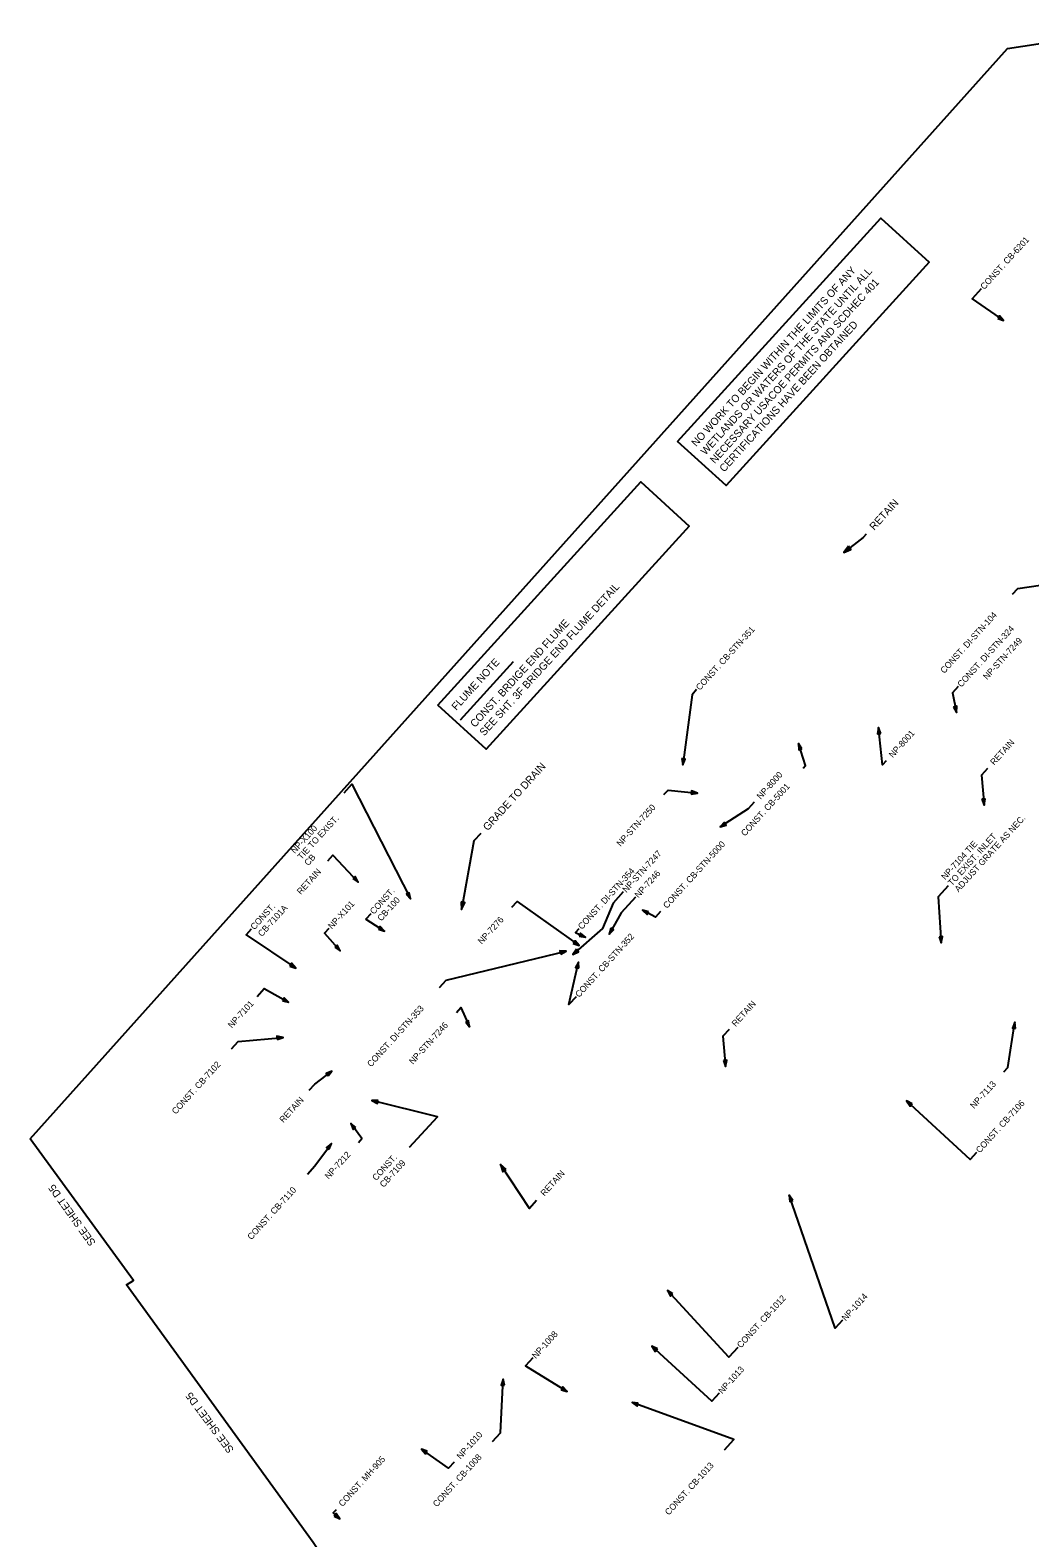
# Model space of a CAD drawing. Extents: x 1608866 to 1610566, y 1091738 to 1093850.
# Drawn here: x 1608866 to 1609658, y 1092457 to 1093652 of the extents above; entities that cross this region are included whole.
import ezdxf

# ---------------------------------------------------------------- set-up
doc = ezdxf.new("R2010")
doc.units = 0
for name, color, linetype in [('NOI', 7, 'Continuous'), ('Plan_Clip', 7, 'Continuous'), ('RD_SHT_MatchLine', 7, 'Continuous'), ('RD_TX_Drainage', 7, 'Continuous')]:
    doc.layers.add(name, color=color, linetype=linetype)

msp = doc.modelspace()

# ---------------------------------------------------------------- linework, layer by layer
at = {"layer": 'NOI'}
for points in [[(1609379, 1093326.2), (1609540, 1093503.2), (1609578.4, 1093468.3), (1609417.4, 1093291.3)], [(1609188.8, 1093117.1), (1609349.8, 1093294.1), (1609388.2, 1093259.2), (1609227.2, 1093082.2)]]:
    msp.add_lwpolyline(points, close=True, dxfattribs=at)
at = {"layer": 'Plan_Clip'}
msp.add_lwpolyline([(1608865.5, 1092773.4), (1609640.6, 1093637.6), (1609736, 1093652.2), (1609859.4, 1093621.4), (1610115.1, 1093602.3), (1610196.6, 1093489.1), (1610193.3, 1093486.6), (1610273.8, 1093378.2), (1610243.5, 1093357.4), (1610329.6, 1093201), (1610402.7, 1093068.4), (1609510.9, 1092089.3), (1609496.9, 1092101.7), (1609489.5, 1092107.9), (1609480.6, 1092093.3), (1609450.3, 1092116), (1609446.7, 1092111), (1609379.8, 1092159.3), (1609135.6, 1092347), (1609149.6, 1092364.4), (1609090, 1092453.4), (1608942, 1092657.6), (1608947.4, 1092661.1)], close=True, dxfattribs=at)
msp.add_lwpolyline([(1608865.5, 1092773.4), (1609640.6, 1093637.6), (1609736, 1093652.2), (1609859.4, 1093621.4), (1610115.1, 1093602.3), (1610196.6, 1093489.1), (1610193.3, 1093486.6), (1610273.8, 1093378.2), (1610243.5, 1093357.4), (1610329.6, 1093201), (1610402.7, 1093068.4), (1609510.9, 1092089.3), (1609496.9, 1092101.7), (1609489.5, 1092107.9), (1609480.6, 1092093.3), (1609450.3, 1092116), (1609446.7, 1092111), (1609379.8, 1092159.3), (1609135.6, 1092347), (1609149.6, 1092364.4), (1609090, 1092453.4), (1608942, 1092657.6), (1608947.4, 1092661.1)], close=True, dxfattribs=at)
msp.add_lwpolyline([(1608865.5, 1092773.4), (1609640.6, 1093637.6), (1609736, 1093652.2), (1609859.4, 1093621.4), (1610115.1, 1093602.3), (1610196.6, 1093489.1), (1610193.3, 1093486.6), (1610273.8, 1093378.2), (1610243.5, 1093357.4), (1610329.6, 1093201), (1610402.7, 1093068.4), (1609510.9, 1092089.3), (1609496.9, 1092101.7), (1609489.5, 1092107.9), (1609480.6, 1092093.3), (1609450.3, 1092116), (1609446.7, 1092111), (1609379.8, 1092159.3), (1609135.6, 1092347), (1609149.6, 1092364.4), (1609090, 1092453.4), (1608942, 1092657.6), (1608947.4, 1092661.1)], close=True, dxfattribs=at)
msp.add_lwpolyline([(1608865.5, 1092773.4), (1609640.6, 1093637.6), (1609736, 1093652.2), (1609859.4, 1093621.4), (1610115.1, 1093602.3), (1610196.6, 1093489.1), (1610193.3, 1093486.6), (1610273.8, 1093378.2), (1610243.5, 1093357.4), (1610329.6, 1093201), (1610402.7, 1093068.4), (1609510.9, 1092089.3), (1609496.9, 1092101.7), (1609489.5, 1092107.9), (1609480.6, 1092093.3), (1609450.3, 1092116), (1609446.7, 1092111), (1609379.8, 1092159.3), (1609135.6, 1092347), (1609149.6, 1092364.4), (1609090, 1092453.4), (1608942, 1092657.6), (1608947.4, 1092661.1)], close=True, dxfattribs=at)
msp.add_lwpolyline([(1608865.5, 1092773.4), (1609640.6, 1093637.6), (1609736, 1093652.2), (1609859.4, 1093621.4), (1610115.1, 1093602.3), (1610196.6, 1093489.1), (1610193.3, 1093486.6), (1610273.8, 1093378.2), (1610243.5, 1093357.4), (1610329.6, 1093201), (1610402.7, 1093068.4), (1609510.9, 1092089.3), (1609496.9, 1092101.7), (1609489.5, 1092107.9), (1609480.6, 1092093.3), (1609450.3, 1092116), (1609446.7, 1092111), (1609379.8, 1092159.3), (1609135.6, 1092347), (1609149.6, 1092364.4), (1609090, 1092453.4), (1608942, 1092657.6), (1608947.4, 1092661.1)], close=True, dxfattribs=at)
msp.add_lwpolyline([(1608865.5, 1092773.4), (1609640.6, 1093637.6), (1609736, 1093652.2), (1609859.4, 1093621.4), (1610115.1, 1093602.3), (1610196.6, 1093489.1), (1610193.3, 1093486.6), (1610273.8, 1093378.2), (1610243.5, 1093357.4), (1610329.6, 1093201), (1610402.7, 1093068.4), (1609510.9, 1092089.3), (1609496.9, 1092101.7), (1609489.5, 1092107.9), (1609480.6, 1092093.3), (1609450.3, 1092116), (1609446.7, 1092111), (1609379.8, 1092159.3), (1609135.6, 1092347), (1609149.6, 1092364.4), (1609090, 1092453.4), (1608942, 1092657.6), (1608947.4, 1092661.1)], close=True, dxfattribs=at)
msp.add_lwpolyline([(1608865.5, 1092773.4), (1609640.6, 1093637.6), (1609736, 1093652.2), (1609859.4, 1093621.4), (1610115.1, 1093602.3), (1610196.6, 1093489.1), (1610193.3, 1093486.6), (1610273.8, 1093378.2), (1610243.5, 1093357.4), (1610329.6, 1093201), (1610402.7, 1093068.4), (1609510.9, 1092089.3), (1609496.9, 1092101.7), (1609489.5, 1092107.9), (1609480.6, 1092093.3), (1609450.3, 1092116), (1609446.7, 1092111), (1609379.8, 1092159.3), (1609135.6, 1092347), (1609149.6, 1092364.4), (1609090, 1092453.4), (1608942, 1092657.6), (1608947.4, 1092661.1)], close=True, dxfattribs=at)
msp.add_lwpolyline([(1608865.5, 1092773.4), (1609640.6, 1093637.6), (1609736, 1093652.2), (1609859.4, 1093621.4), (1610115.1, 1093602.3), (1610196.6, 1093489.1), (1610193.3, 1093486.6), (1610273.8, 1093378.2), (1610243.5, 1093357.4), (1610329.6, 1093201), (1610402.7, 1093068.4), (1609510.9, 1092089.3), (1609496.9, 1092101.7), (1609489.5, 1092107.9), (1609480.6, 1092093.3), (1609450.3, 1092116), (1609446.7, 1092111), (1609379.8, 1092159.3), (1609135.6, 1092347), (1609149.6, 1092364.4), (1609090, 1092453.4), (1608942, 1092657.6), (1608947.4, 1092661.1)], close=True, dxfattribs=at)
at = {"layer": 'RD_TX_Drainage'}
msp.add_line((1609206.9, 1093105.6), (1609248.9, 1093151.7), dxfattribs=at)
for points in [[(1609619.7, 1093447.1), (1609612.5, 1093439.2), (1609637.5, 1093422)], [(1609528.4, 1093252.7), (1609526, 1093250.1), (1609510.8, 1093238.3)], [(1609644.6, 1093205.2), (1609648.8, 1093209.8), (1609742.1, 1093223.5)], [(1609601.5, 1093131.9), (1609596.9, 1093126.9), (1609600.1, 1093111.3)], [(1609394, 1093129.5), (1609390.4, 1093125.5), (1609383, 1093069.9)], [(1609544.4, 1093073.1), (1609541.4, 1093069.8), (1609538.3, 1093099.4)], [(1609478.4, 1093067.2), (1609480.5, 1093069.5), (1609474.7, 1093086.8)], [(1609624.8, 1093067.1), (1609620, 1093061.8), (1609622.1, 1093037.9)], [(1609114.5, 1093047.7), (1609120.6, 1093054.5), (1609167.1, 1092963.6)], [(1609368.1, 1093046.3), (1609371.4, 1093049.9), (1609394.8, 1093047.5)], [(1609439.7, 1093040.2), (1609434.9, 1093034.9), (1609412.8, 1093020.7)], [(1609222.8, 1093015.5), (1609217.5, 1093009.6), (1609207.7, 1092955.2)], [(1609101.5, 1092993.8), (1609105.6, 1092998.3), (1609125.6, 1092977)], [(1609335.9, 1092969.2), (1609327.8, 1092960.2), (1609319.4, 1092940.1), (1609296, 1092919.6)], [(1609345.5, 1092965), (1609334.1, 1092952.5), (1609331.6, 1092947.8), (1609324.6, 1092935.6)], [(1609593.4, 1092973.9), (1609585.5, 1092965.3), (1609587.9, 1092928.8)], [(1609135.6, 1092951.9), (1609131.8, 1092947.7), (1609146.5, 1092938)], [(1609247.4, 1092957), (1609251.7, 1092961.7), (1609300.8, 1092926.6)], [(1609365.4, 1092953.6), (1609361.4, 1092949.2), (1609351, 1092954.6)], [(1609102.3, 1092940.3), (1609099, 1092936.6), (1609111.3, 1092922.5)], [(1609300.6, 1092940), (1609297.9, 1092937), (1609305.8, 1092933.3)], [(1609040.9, 1092939.6), (1609036.8, 1092935.1), (1609076.2, 1092908.8)], [(1609190.1, 1092893.3), (1609195.5, 1092899.2), (1609290.7, 1092922.3)], [(1609298.4, 1092886.1), (1609292.8, 1092879.9), (1609300.4, 1092913.6)], [(1609045.5, 1092886.4), (1609051.1, 1092892.6), (1609070.5, 1092881.7)], [(1609203.5, 1092873.5), (1609207.1, 1092877.5), (1609214, 1092862.1)], [(1609419.8, 1092860), (1609414.9, 1092854.7), (1609417, 1092830.8)], [(1609637.6, 1092826.6), (1609640.7, 1092829.9), (1609646.4, 1092865.8)], [(1609025.2, 1092844.8), (1609030.4, 1092850.5), (1609066.2, 1092853.9)], [(1609086.7, 1092811.9), (1609091.2, 1092816.8), (1609104.9, 1092827.2)], [(1609166.4, 1092766.8), (1609188.5, 1092791), (1609136.5, 1092803.8)], [(1609616.1, 1092762.7), (1609611, 1092757.2), (1609560.6, 1092803.5)], [(1609125.8, 1092770.6), (1609128.5, 1092773.6), (1609119.9, 1092785.5)], [(1609085.4, 1092745.5), (1609091.3, 1092752), (1609104.5, 1092769.8)], [(1609267.2, 1092724.5), (1609261.5, 1092718.3), (1609238.4, 1092753.1)], [(1609509.8, 1092629.6), (1609504, 1092623.3), (1609467.5, 1092728.9)], [(1609426.7, 1092608.1), (1609419.7, 1092600.4), (1609370.9, 1092653.3)], [(1609411.9, 1092571.9), (1609406.2, 1092565.6), (1609358.6, 1092609.2)], [(1609264.1, 1092599.8), (1609258.3, 1092593.4), (1609291.4, 1092573.2)], [(1609232.2, 1092533.5), (1609238.5, 1092540.4), (1609240.7, 1092583)], [(1609416.2, 1092527), (1609423.6, 1092535.1), (1609342.8, 1092564.5)], [(1609201.7, 1092517.1), (1609197.4, 1092512.3), (1609175.8, 1092527.5)], [(1609108.1, 1092479.5), (1609105.7, 1092476.9), (1609111, 1092472.2)]]:
    msp.add_lwpolyline(points, dxfattribs=at)
for points in [[(1609632.8, 1093423.7), (1609637.5, 1093422), (1609634.3, 1093425.8)], [(1609514.4, 1093243.1), (1609510.8, 1093238.3), (1609516.3, 1093240.6)], [(1609597.8, 1093115.7), (1609600.1, 1093111.3), (1609600.4, 1093116.3)], [(1609540.1, 1093094.7), (1609538.3, 1093099.4), (1609537.5, 1093094.5)], [(1609477.4, 1093082.6), (1609474.7, 1093086.8), (1609475, 1093081.8)], [(1609382.4, 1093074.9), (1609383, 1093069.9), (1609384.9, 1093074.5)], [(1609389.8, 1093046.7), (1609394.8, 1093047.5), (1609390.1, 1093049.2)], [(1609620.3, 1093042.6), (1609622.1, 1093037.9), (1609622.9, 1093042.8)], [(1609416.2, 1093024.4), (1609412.8, 1093020.7), (1609417.6, 1093022.2)], [(1609121.3, 1092979.7), (1609125.6, 1092977), (1609123.2, 1092981.4)], [(1609163.8, 1092967.3), (1609167.1, 1092963.6), (1609166.1, 1092968.5)], [(1609207.2, 1092961.2), (1609207.7, 1092955.2), (1609210.2, 1092960.7)], [(1609355.9, 1092953.5), (1609351, 1092954.6), (1609354.7, 1092951.2)], [(1609141.7, 1092939.6), (1609146.5, 1092938), (1609143.2, 1092941.8)], [(1609325.9, 1092940.4), (1609324.6, 1092935.6), (1609328.1, 1092939.1)], [(1609296.2, 1092928.3), (1609300.8, 1092926.6), (1609297.7, 1092930.4)], [(1609300.9, 1092934.2), (1609305.8, 1092933.3), (1609302, 1092936.5)], [(1609586.3, 1092933.6), (1609587.9, 1092928.8), (1609588.9, 1092933.7)], [(1609107.1, 1092925.3), (1609111.3, 1092922.5), (1609109.1, 1092927)], [(1609286.3, 1092919.9), (1609290.7, 1092922.3), (1609285.7, 1092922.4)], [(1609298.8, 1092923.7), (1609296, 1092919.6), (1609300.5, 1092921.8)], [(1609071.4, 1092910.4), (1609076.2, 1092908.8), (1609072.9, 1092912.6)], [(1609300.6, 1092908.6), (1609300.4, 1092913.6), (1609298.1, 1092909.2)], [(1609065.6, 1092882.9), (1609070.5, 1092881.7), (1609066.9, 1092885.2)], [(1609210.9, 1092866), (1609214, 1092862.1), (1609213.2, 1092867.1)], [(1609646.9, 1092860.9), (1609646.4, 1092865.8), (1609644.4, 1092861.3)], [(1609061.5, 1092852.2), (1609066.2, 1092853.9), (1609061.2, 1092854.7)], [(1609415.3, 1092835.5), (1609417, 1092830.8), (1609417.9, 1092835.7)], [(1609101.8, 1092823.3), (1609104.9, 1092827.2), (1609100.2, 1092825.3)], [(1609141.5, 1092803.9), (1609136.5, 1092803.8), (1609140.9, 1092801.4)], [(1609565, 1092801.2), (1609560.6, 1092803.5), (1609563.3, 1092799.3)], [(1609123.8, 1092782.4), (1609119.9, 1092785.5), (1609121.7, 1092780.8)], [(1609102.7, 1092765.2), (1609104.5, 1092769.8), (1609100.6, 1092766.7)], [(1609242.9, 1092749.1), (1609238.4, 1092753.1), (1609240.3, 1092747.4)], [(1609470.3, 1092724.7), (1609467.5, 1092728.9), (1609467.9, 1092723.9)], [(1609375.2, 1092650.6), (1609370.9, 1092653.3), (1609373.3, 1092648.8)], [(1609363.1, 1092606.9), (1609358.6, 1092609.2), (1609361.3, 1092605)], [(1609241.7, 1092578.1), (1609240.7, 1092583), (1609239.1, 1092578.2)], [(1609286.6, 1092574.6), (1609291.4, 1092573.2), (1609287.9, 1092576.9)], [(1609347.8, 1092564), (1609342.8, 1092564.5), (1609346.9, 1092561.6)], [(1609180.5, 1092525.8), (1609175.8, 1092527.5), (1609179, 1092523.7)], [(1609106.5, 1092474.4), (1609111, 1092472.2), (1609108.2, 1092476.4)]]:
    msp.add_lwpolyline(points, close=True, dxfattribs=at)

# ---------------------------------------------------------------- texts
at = {"layer": 'NOI'}
for s, p in [('NO WORK TO BEGIN WITHIN THE LIMITS OF ANY', (1609393.7, 1093321.7)), ('WETLANDS OR WATERS OF THE STATE UNTIL ALL', (1609401.1, 1093315)), ('NECESSARY USACOE PERMITS AND SCDHEC 401', (1609408.5, 1093308.2)), ('CERTIFICATIONS HAVE BEEN OBTAINED', (1609415.9, 1093301.5)), ('SEE SHT. 3F BRIDGE END FLUME DETAIL', (1609225.7, 1093092.4)), ('CONST. BRDIGE END FLUME', (1609218.3, 1093099.1)), ('FLUME NOTE', (1609203.5, 1093112.6))]:
    msp.add_text(s, height=6, rotation=47.7153, dxfattribs=at).set_placement(p)
at = {"layer": 'RD_SHT_MatchLine'}
for rotation, p in [(125.5072, (1608917.8, 1092691.2)), (126.6022, (1609027.4, 1092527.1))]:
    msp.add_text('SEE SHEET D5', height=6, rotation=rotation, dxfattribs=at).set_placement(p)
at = {"layer": 'RD_TX_Drainage'}
for s, height, p in [('CONST. CB-6201', 5, (1609622.2, 1093446.2)), ('RETAIN', 6, (1609534.9, 1093255.4)), ('CONST. DI-STN-104', 5, (1609590.4, 1093141.9)), ('CONST. CB-STN-351', 5, (1609396.6, 1093128.5)), ('CONST. DI-STN-324', 5, (1609604, 1093131)), ('NP-STN-7249', 5, (1609624.4, 1093137)), ('NP-8001', 5, (1609549.6, 1093075.1)), ('RETAIN', 5, (1609630, 1093069.2)), ('GRADE TO DRAIN', 6, (1609228.4, 1093017.2)), ('NP-8000', 5, (1609444.9, 1093042.2)), ('CONST. CB-5001', 5, (1609432.4, 1093012.9)), ('NP-STN-7250', 5, (1609333.7, 1093004.8)), ('TIE TO EXIST.', 5, (1609080.8, 1092994.3)), (' ADJUST GRATE AS NEC.', 5, (1609600.5, 1092967.3)), ('NP-X100', 5, (1609075.4, 1092999.2)), (' TO EXIST. INLET', 5, (1609595.2, 1092972.2)), ('NP-STN-7247', 5, (1609338.4, 1092968.2)), ('CONST. CB-STN-5000', 5, (1609370.6, 1092955.6)), (' NP-7104 TIE', 5, (1609589.9, 1092977)), ('RETAIN', 5, (1609080.2, 1092966.7)), ('CB', 5, (1609086.1, 1092989.5)), ('CONST. DI-STN-354', 5, (1609303.1, 1092939)), ('NP-7246', 5, (1609348, 1092964)), ('CONST.', 5, (1609138.1, 1092951)), ('CB-100', 5, (1609144, 1092945.6)), ('CONST.', 5, (1609043.4, 1092938.7)), ('CB-7101A', 5, (1609049.3, 1092933.3)), ('NP-X101', 5, (1609104.9, 1092939.3)), ('NP-7276', 5, (1609223.7, 1092927.3)), ('CONST. CB-STN-352', 5, (1609300.9, 1092885.1)), ('NP-7101', 5, (1609025.5, 1092860.8)), ('RETAIN', 5, (1609425, 1092862)), ('CONST. DI-STN-353', 5, (1609135.9, 1092830)), ('NP-STN-7246', 5, (1609169.1, 1092832.1)), ('CONST. CB-7102', 5, (1608981, 1092792.5)), ('NP-7113', 5, (1609614.1, 1092797)), ('RETAIN', 5, (1609066.4, 1092785.8)), ('CONST. CB-7106', 5, (1609618.6, 1092761.8)), ('NP-7212', 5, (1609102.3, 1092741.1)), ('CONST.', 5, (1609140, 1092739.9)), ('CB-7109', 5, (1609145.9, 1092734.5)), ('RETAIN', 5, (1609273.4, 1092727.6)), ('CONST. CB-7110', 5, (1609041, 1092693)), ('CONST. CB-1012', 5, (1609429.2, 1092607.2)), ('NP-1014', 5, (1609512.3, 1092628.7)), ('NP-1008', 5, (1609266.6, 1092598.8)), ('NP-1013', 5, (1609414.4, 1092570.9)), ('NP-1010', 5, (1609206.9, 1092519.1)), ('CONST. MH-905', 5, (1609113.3, 1092481.5)), ('CONST. CB-1008', 5, (1609188, 1092481.2)), ('CONST. CB-1013', 5, (1609372, 1092474.7))]:
    msp.add_text(s, height=height, rotation=47.7138, dxfattribs=at).set_placement(p)

doc.saveas('drawing.dxf')
